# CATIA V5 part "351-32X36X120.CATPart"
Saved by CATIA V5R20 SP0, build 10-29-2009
Part number: 351-32X36X120
Definition: NONE
Nomenclature: 351-32X36X120
Source: Unknown
Description: 351-32X36X120
Bounding box of the stored display mesh (mm): x -7 to 113, y -22.5 to 22.5, z -22.5 to 22.5
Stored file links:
  C:\Users\Utente\Desktop\IO LAVORO\3D X SITO CF\X SITO\PLASTICA\351\351-32X36X120.CATPart
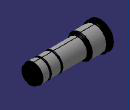
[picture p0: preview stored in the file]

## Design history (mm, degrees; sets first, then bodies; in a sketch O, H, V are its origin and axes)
Body1 "351-32X36X120" (main body)
  Solid1: solid without history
